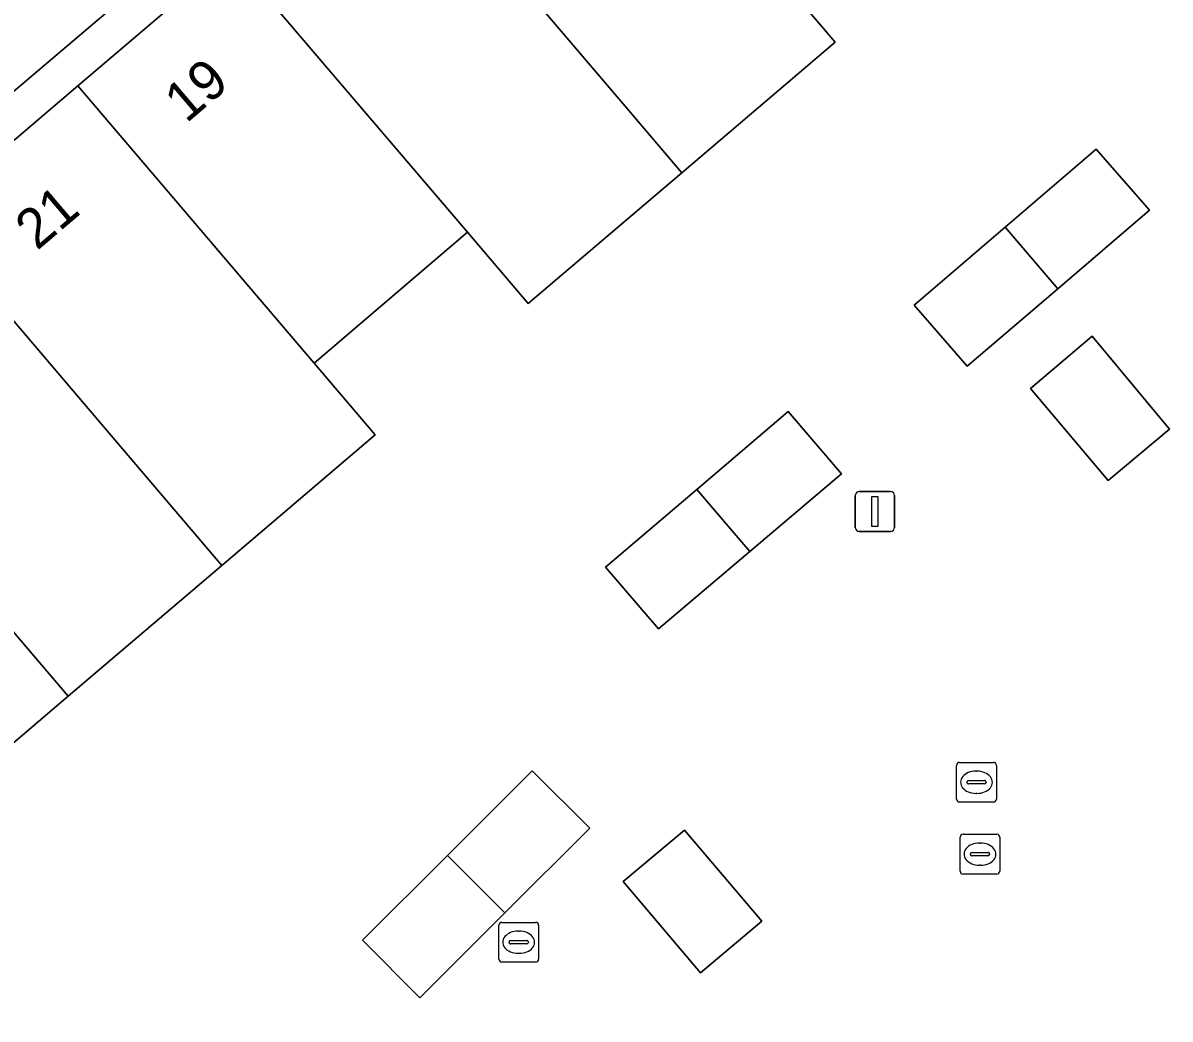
# Model space of a CAD drawing. Extents: x 160377 to 161131, y 383938 to 384853.
# Drawn here: x 160713.26 to 160742.14, y 384618.33 to 384643.41 of the extents above; entities that cross this region are included whole.
import ezdxf

# ---------------------------------------------------------------- set-up
doc = ezdxf.new("R2010")
doc.units = 0
for name, color, linetype in [('IMGEO_Erf', 7, 'Continuous'), ('IMGEO_Kolk', 7, 'Continuous'), ('IMGEO_Lichtmast', 7, 'Continuous'), ('IMGEO_Pand', 7, 'Continuous'), ('IMGEO_Pand_nummerreeks', 7, 'Continuous'), ('IMGEO_Rioolput', 7, 'Continuous'), ('IMGEO_Voetgangersgebied_open', 7, 'Continuous')]:
    doc.layers.add(name, color=color, linetype=linetype)

msp = doc.modelspace()

# ---------------------------------------------------------------- linework, layer by layer
at = {"layer": 'IMGEO_Erf'}
for points in [[(160814.707, 384533.039), (160805.221, 384581.626), (160804.227, 384586.696), (160801.827, 384589.484), (160785.555, 384608.533), (160784.593, 384609.659), (160759.221, 384639.361), (160756.612, 384642.415), (160753.096, 384646.531), (160752.089, 384647.71), (160738.611, 384663.488), (160738.585, 384663.466), (160731.208, 384657.183), (160728.177, 384654.568), (160723.454, 384650.553), (160720.379, 384647.933), (160715.683, 384643.941), (160712.616, 384641.352)], [(160710.78, 384638.533), (160714.642, 384641.826), (160718.504, 384645.12), (160722.366, 384648.414), (160726.228, 384651.708), (160730.09, 384655.002), (160733.946, 384658.29), (160738.451, 384662.132), (160746.358, 384652.867), (160741.855, 384649.024), (160739.907, 384651.306), (160736.043, 384648.014), (160732.179, 384644.723), (160733.708, 384642.928), (160729.844, 384639.636), (160725.98, 384636.345), (160724.452, 384638.139), (160720.588, 384634.847), (160722.127, 384633.04), (160718.264, 384629.748), (160714.4, 384626.456), (160710.537, 384623.165)]]:
    msp.add_lwpolyline(points, dxfattribs=at)
for points in [[(160739.315, 384636.719), (160737.032, 384634.766), (160735.694, 384636.303), (160737.988, 384638.268), (160740.281, 384640.233), (160741.625, 384638.696)], [(160740.58, 384631.89), (160738.627, 384634.209), (160740.175, 384635.52), (160742.128, 384633.182)], [(160731.558, 384630.099), (160729.263, 384628.151), (160727.923, 384629.705), (160730.225, 384631.665), (160732.526, 384633.625), (160733.866, 384632.058)], [(160725.391, 384620.997), (160723.252, 384618.861), (160721.807, 384620.311), (160723.945, 384622.445), (160726.079, 384624.576), (160727.53, 384623.133)], [(160730.319, 384619.489), (160728.366, 384621.789), (160729.912, 384623.087), (160731.857, 384620.79)]]:
    msp.add_lwpolyline(points, close=True, dxfattribs=at)
at = {"layer": 'IMGEO_Kolk'}
for p, q in [((160736.852, 384622.052), (160736.852, 384622.904)), ((160736.927, 384622.978), (160737.779, 384622.978)), ((160737.853, 384622.904), (160737.853, 384622.052)), ((160737.34, 384622.758), (160737.365, 384622.758)), ((160737.111, 384622.472), (160737.111, 384622.484)), ((160737.549, 384622.435), (160737.151, 384622.435)), ((160737.154, 384622.521), (160737.552, 384622.521)), ((160737.595, 384622.484), (160737.595, 384622.472)), ((160737.779, 384621.978), (160736.927, 384621.978)), ((160737.363, 384622.198), (160737.338, 384622.198)), ((160725.239, 384619.835), (160725.239, 384620.687)), ((160725.314, 384620.761), (160726.166, 384620.761)), ((160725.727, 384620.541), (160725.752, 384620.541)), ((160726.24, 384620.687), (160726.24, 384619.835)), ((160725.498, 384620.255), (160725.498, 384620.267)), ((160725.541, 384620.304), (160725.939, 384620.304)), ((160725.982, 384620.267), (160725.982, 384620.255)), ((160725.936, 384620.218), (160725.538, 384620.218)), ((160725.75, 384619.981), (160725.725, 384619.981)), ((160726.166, 384619.761), (160725.314, 384619.761))]:
    msp.add_line(p, q, dxfattribs=at)
for points in [[(160736.852, 384622.052), (160736.852, 384622.904)], [(160736.927, 384622.978), (160737.779, 384622.978)], [(160737.853, 384622.904), (160737.853, 384622.052)], [(160737.779, 384621.978), (160736.927, 384621.978)], [(160725.239, 384619.835), (160725.239, 384620.687)], [(160725.314, 384620.761), (160726.166, 384620.761)], [(160726.24, 384620.687), (160726.24, 384619.835)], [(160726.166, 384619.761), (160725.314, 384619.761)]]:
    msp.add_lwpolyline(points, dxfattribs=at)
for centre, radius, start, end in [((160736.929, 384622.902), 0.0765, 91.552, 178.448), ((160736.929, 384622.902), 0.0765, 91.552, 178.448), ((160737.777, 384622.902), 0.0765, 1.552, 88.448), ((160737.777, 384622.902), 0.0765, 1.552, 88.448), ((160737.151, 384622.481), 0.0403, 85.8775, 175.7526), ((160737.148, 384622.471), 0.0366, 178.938, 274.7102), ((160737.552, 384622.478), 0.043, 264.8664, 352.4533), ((160737.556, 384622.483), 0.0386, 1.7309, 96.639), ((160736.929, 384622.054), 0.0765, 181.552, 268.448), ((160736.929, 384622.054), 0.0765, 181.552, 268.448), ((160737.777, 384622.054), 0.0765, 271.552, 358.448), ((160737.777, 384622.054), 0.0765, 271.552, 358.448), ((160725.316, 384620.685), 0.0765, 91.552, 178.448), ((160725.316, 384620.685), 0.0765, 91.552, 178.448), ((160726.164, 384620.685), 0.0765, 1.552, 88.448), ((160726.164, 384620.685), 0.0765, 1.552, 88.448), ((160725.538, 384620.264), 0.0403, 85.8775, 175.7526), ((160725.535, 384620.254), 0.0366, 178.938, 274.7102), ((160725.939, 384620.261), 0.043, 264.8664, 352.4533), ((160725.943, 384620.266), 0.0386, 1.7309, 96.639), ((160725.316, 384619.837), 0.0765, 181.552, 268.448), ((160725.316, 384619.837), 0.0765, 181.552, 268.448), ((160726.164, 384619.837), 0.0765, 271.552, 358.448), ((160726.164, 384619.837), 0.0765, 271.552, 358.448)]:
    msp.add_arc(centre, radius, start, end, dxfattribs=at)
for centre, major_axis, ratio, start_param, end_param in [((160737.339, 384622.478), (-0.387, 0.002), 0.722429, 4.712389, 7.853982), ((160737.364, 384622.478), (-0.39, 0.002), 0.717154, 1.570796, 4.712389), ((160725.726, 384620.261), (-0.387, 0.002), 0.722429, 4.712389, 7.853982), ((160725.751, 384620.261), (-0.39, 0.002), 0.717154, 1.570796, 4.712389)]:
    msp.add_ellipse(centre, major_axis=major_axis, ratio=ratio, start_param=start_param, end_param=end_param, dxfattribs=at)
at = {"layer": 'IMGEO_Lichtmast'}
for p, q in [((160734.214, 384630.708), (160734.214, 384631.508)), ((160734.214, 384631.508), (160734.214, 384630.708)), ((160734.314, 384631.608), (160735.104, 384631.608)), ((160735.104, 384631.608), (160734.314, 384631.608)), ((160735.204, 384631.508), (160735.204, 384630.708)), ((160735.204, 384630.708), (160735.204, 384631.508)), ((160735.104, 384630.608), (160734.314, 384630.608)), ((160734.314, 384630.608), (160735.104, 384630.608))]:
    msp.add_line(p, q, dxfattribs=at)
msp.add_lwpolyline([(160734.634, 384631.483), (160734.784, 384631.483), (160734.784, 384630.733), (160734.634, 384630.733), (160734.634, 384631.483)], dxfattribs=at)
for centre, start, end in [((160734.314, 384631.508), 90, 180), ((160734.314, 384631.508), 90, 180), ((160735.104, 384631.508), 0, 90), ((160735.104, 384631.508), 360, 90), ((160734.314, 384630.708), 180, 270), ((160734.314, 384630.708), 180, 270), ((160735.104, 384630.708), 270, 0), ((160735.104, 384630.708), 270, 0)]:
    msp.add_arc(centre, 0.1, start, end, dxfattribs=at)
at = {"layer": 'IMGEO_Pand'}
for points in [[(160726.228, 384651.708), (160722.366, 384648.414), (160728.315, 384641.431), (160729.844, 384639.636), (160733.708, 384642.928), (160732.179, 384644.723)], [(160722.366, 384648.414), (160718.504, 384645.12), (160724.452, 384638.139), (160725.98, 384636.345), (160729.844, 384639.636), (160728.315, 384641.431)], [(160718.504, 384645.12), (160714.642, 384641.826), (160720.588, 384634.847), (160724.452, 384638.139)], [(160714.642, 384641.826), (160710.78, 384638.533), (160716.721, 384631.559), (160718.264, 384629.748), (160722.127, 384633.04), (160720.588, 384634.847)], [(160741.625, 384638.696), (160740.281, 384640.233), (160737.988, 384638.268), (160739.315, 384636.719)], [(160710.78, 384638.533), (160706.918, 384635.239), (160712.86, 384628.264), (160714.4, 384626.456), (160718.264, 384629.748), (160716.721, 384631.559)], [(160739.315, 384636.719), (160737.988, 384638.268), (160735.694, 384636.303), (160737.032, 384634.766)], [(160740.175, 384635.52), (160738.627, 384634.209), (160740.58, 384631.89), (160742.128, 384633.182)], [(160706.918, 384635.239), (160703.054, 384631.943), (160708.996, 384624.972), (160710.537, 384623.165), (160714.4, 384626.456), (160712.86, 384628.264)], [(160733.866, 384632.058), (160732.526, 384633.625), (160730.225, 384631.665), (160731.558, 384630.099)], [(160731.558, 384630.099), (160730.225, 384631.665), (160727.923, 384629.705), (160729.263, 384628.151)], [(160727.53, 384623.133), (160726.079, 384624.576), (160723.945, 384622.445), (160725.391, 384620.997)], [(160728.366, 384621.789), (160730.319, 384619.489), (160731.857, 384620.79), (160729.912, 384623.087)], [(160725.391, 384620.997), (160723.945, 384622.445), (160721.807, 384620.311), (160723.252, 384618.861)]]:
    msp.add_lwpolyline(points, close=True, dxfattribs=at)
at = {"layer": 'IMGEO_Rioolput'}
for p, q in [((160736.765, 384623.863), (160736.765, 384624.715)), ((160736.84, 384624.789), (160737.692, 384624.789)), ((160737.253, 384624.569), (160737.278, 384624.569)), ((160737.766, 384624.715), (160737.766, 384623.863)), ((160737.024, 384624.283), (160737.024, 384624.295)), ((160737.067, 384624.332), (160737.465, 384624.332)), ((160737.508, 384624.295), (160737.508, 384624.283)), ((160737.462, 384624.246), (160737.064, 384624.246)), ((160737.276, 384624.009), (160737.251, 384624.009)), ((160737.692, 384623.789), (160736.84, 384623.789))]:
    msp.add_line(p, q, dxfattribs=at)
for points in [[(160736.765, 384623.863), (160736.765, 384624.715)], [(160736.84, 384624.789), (160737.692, 384624.789)], [(160737.766, 384624.715), (160737.766, 384623.863)], [(160737.692, 384623.789), (160736.84, 384623.789)]]:
    msp.add_lwpolyline(points, dxfattribs=at)
for centre, radius, start, end in [((160736.842, 384624.713), 0.0765, 91.552, 178.448), ((160736.842, 384624.713), 0.0765, 91.552, 178.448), ((160737.69, 384624.713), 0.0765, 1.552, 88.448), ((160737.69, 384624.713), 0.0765, 1.552, 88.448), ((160737.064, 384624.292), 0.0403, 85.8775, 175.7526), ((160737.061, 384624.282), 0.0366, 178.938, 274.7102), ((160737.465, 384624.289), 0.043, 264.8664, 352.4533), ((160737.469, 384624.294), 0.0386, 1.7309, 96.639), ((160736.842, 384623.865), 0.0765, 181.552, 268.448), ((160736.842, 384623.865), 0.0765, 181.552, 268.448), ((160737.69, 384623.865), 0.0765, 271.552, 358.448), ((160737.69, 384623.865), 0.0765, 271.552, 358.448)]:
    msp.add_arc(centre, radius, start, end, dxfattribs=at)
for centre, major_axis, ratio, start_param, end_param in [((160737.252, 384624.289), (-0.387, 0.002), 0.722429, 4.712389, 7.853982), ((160737.277, 384624.289), (-0.39, 0.002), 0.717154, 1.570796, 4.712389)]:
    msp.add_ellipse(centre, major_axis=major_axis, ratio=ratio, start_param=start_param, end_param=end_param, dxfattribs=at)
at = {"layer": 'IMGEO_Voetgangersgebied_open'}
msp.add_lwpolyline([(160710.66, 384643.716), (160712.616, 384641.352), (160715.683, 384643.941), (160713.716, 384646.315), (160718.375, 384650.288), (160720.379, 384647.933), (160723.454, 384650.553), (160721.435, 384652.883), (160726.14, 384656.932), (160728.177, 384654.568), (160731.208, 384657.183), (160729.194, 384659.54), (160730.884, 384660.985), (160736.564, 384665.84), (160738.544, 384663.515), (160738.585, 384663.466), (160738.611, 384663.488), (160741.8, 384666.319), (160734.733, 384674.665)], dxfattribs=at)

# ---------------------------------------------------------------- texts
at = {"layer": 'IMGEO_Pand_nummerreeks'}
for s, p in [('19', (160717.369, 384640.867)), ('21', (160713.612, 384637.663))]:
    msp.add_text(s, height=1, rotation=40.4565, dxfattribs=at).set_placement(p)

doc.saveas('drawing.dxf')
